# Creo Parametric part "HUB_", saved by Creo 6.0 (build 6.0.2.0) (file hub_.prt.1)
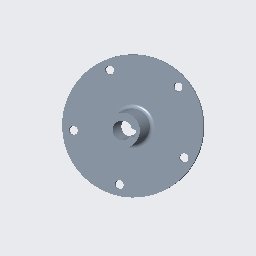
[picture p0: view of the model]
Units: Inch lbm Second (Pro/E Default); INCH, POUND, SECS

Created from: INLBS_PART_SOLID.PRT

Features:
  1. datum plane "RIGHT"
  2. datum plane "TOP"
  3. datum plane "FRONT"
  4. coordinate system
  5. sketch "Sketch 1"
  6. extrusion "Extrude 1"
  7. sketch "Sketch 2"
  8. extrusion "Extrude 2"
  9. sketch "Sketch 3"
  10. extruded cut "Extrude 3"
  11. sketch "Sketch 4"
  12. extruded cut "Extrude 4"
  13. sketch "Sketch 5"
  14. pattern "Pattern 1"
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
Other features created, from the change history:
  extruded cut "Extrude 5"
  datum axis "A_5"
  extruded cut "Extrude 5 [2]"
  extruded cut "Extrude 5 [3]"
  extruded cut "Extrude 5 [4]"
  extruded cut "Extrude 5 [5]"
  round "Round 1"

Surfaces: 9 cylinder, 7 plane, 2 torus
